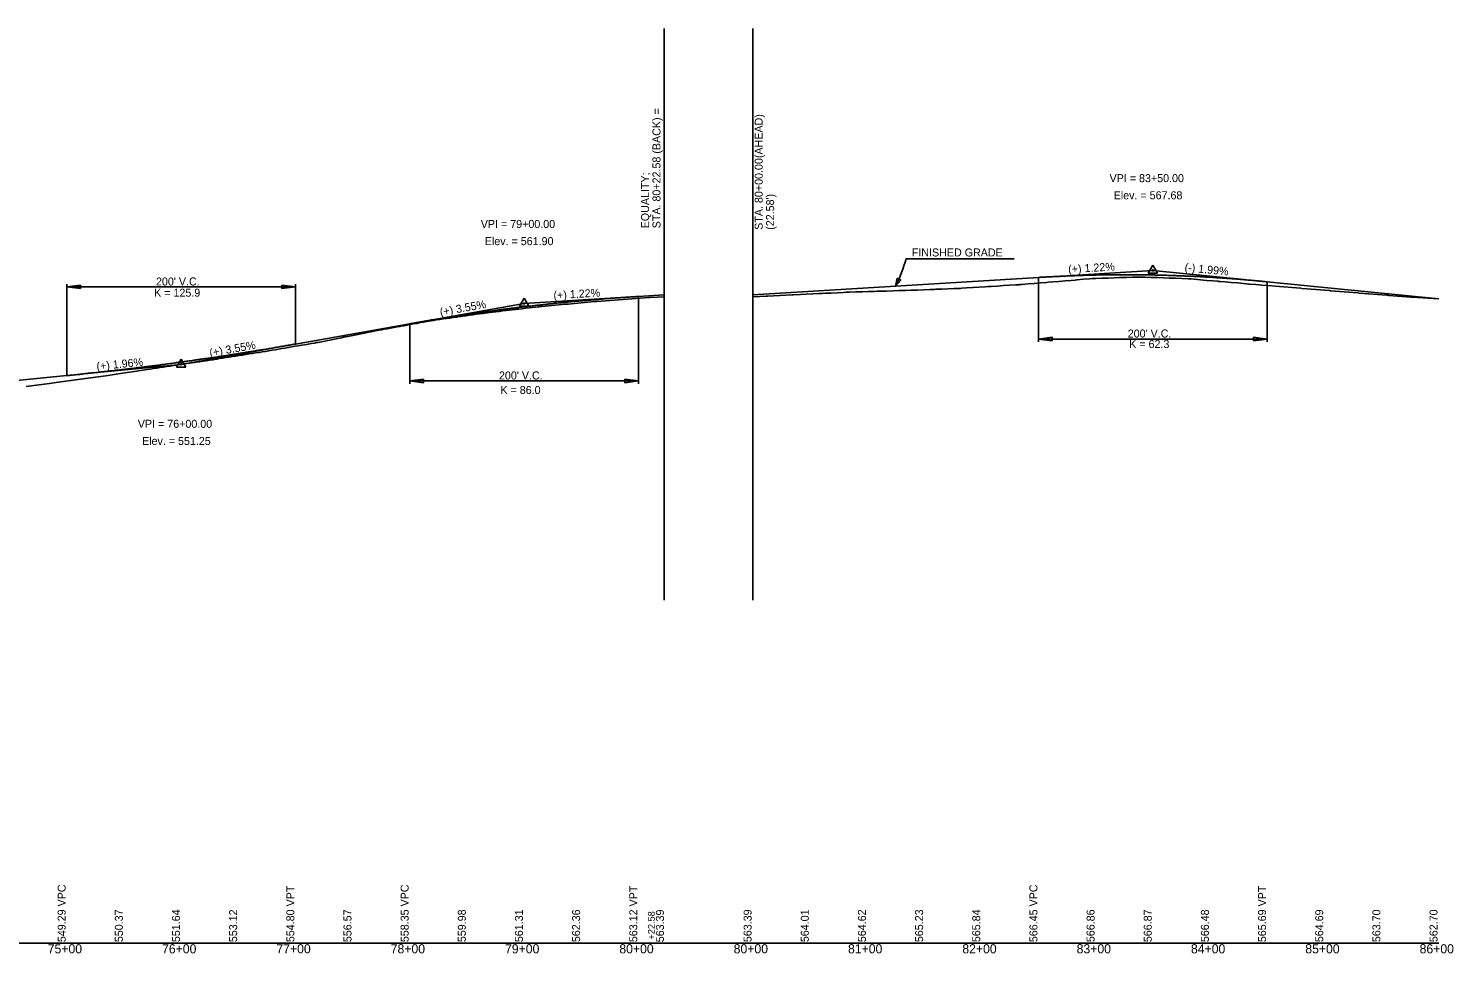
# Model space of a CAD drawing. Extents: x 49922 to 54713, y 49991 to 62800.
# Drawn here: x 53466 to 54713, y 61991 to 62800 of the extents above; entities that cross this region are included whole.
import ezdxf

# ---------------------------------------------------------------- set-up
doc = ezdxf.new("R2010")
doc.units = 0
for name, color, linetype in [('RD_DDB_GradeTX', 7, 'Continuous'), ('RD_DDB_Profile_EX', 7, 'Continuous'), ('RD_DDB_Profile_Lbl', 7, 'Continuous'), ('RD_DDB_Profile_PR', 7, 'Continuous'), ('RD_DDB_StaTX', 7, 'Continuous'), ('RD_DDB_StripGrade', 7, 'Continuous'), ('RD_DDB_VCLbl', 7, 'Continuous'), ('RD_GPK_Profile_Cell', 7, 'Continuous'), ('RD_TX_Profile', 7, 'Continuous')]:
    doc.layers.add(name, color=color, linetype=linetype)

msp = doc.modelspace()

# ---------------------------------------------------------------- linework, layer by layer
at = {"layer": 'RD_DDB_GradeTX'}
for p, q in [((54370.1, 62583.5), (54450, 62588.4)), ((54446, 62586.1), (54450, 62593)), ((54446, 62586.1), (54454, 62586.1)), ((54450, 62593), (54454, 62586.1)), ((54529.6, 62580.5), (54450, 62588.4)), ((53896, 62557.2), (53900, 62564.1)), ((53979.9, 62564.4), (53900, 62559.5)), ((53900, 62564.1), (53904, 62557.2)), ((53821.2, 62545.5), (53900, 62559.5)), ((53896, 62557.2), (53904, 62557.2)), ((53596, 62503.9), (53600, 62510.8)), ((53678.8, 62520.2), (53600, 62506.2)), ((53600, 62510.8), (53604, 62503.9)), ((53520.4, 62498.4), (53600, 62506.2)), ((53596, 62503.9), (53604, 62503.9))]:
    msp.add_line(p, q, dxfattribs=at)
for centre in [(54450, 62588.4), (53900, 62559.5), (53600, 62506.2)]:
    msp.add_circle(centre, 0.529, dxfattribs=at)
at = {"layer": 'RD_DDB_Profile_EX'}
for points in [[(54100, 62565.4), (54111.6, 62565.9), (54112.8, 62566), (54134.4, 62566.9), (54135.7, 62567), (54141.7, 62567.3), (54147.1, 62567.6), (54152.5, 62567.8), (54157.9, 62568.1), (54158.6, 62568.2), (54160.7, 62568.2), (54163.3, 62568.4), (54168.6, 62568.6), (54174, 62568.9), (54179.4, 62569.2), (54181.6, 62569.3), (54183.8, 62569.4), (54184.8, 62569.4), (54190.2, 62569.6), (54195.6, 62569.7), (54200.9, 62569.9), (54206, 62570), (54206.3, 62570), (54208.8, 62570.1), (54211.7, 62570.2), (54217.1, 62570.3), (54222.5, 62570.5), (54227.8, 62570.7), (54230.7, 62570.7), (54233.2, 62570.8), (54233.6, 62570.9), (54238.6, 62571), (54244, 62571.2), (54249.4, 62571.5), (54254.8, 62571.7), (54255.7, 62571.7), (54258.6, 62571.8), (54259.1, 62571.8), (54260.1, 62571.9), (54265.5, 62572.1), (54270.9, 62572.3), (54276.3, 62572.5), (54281, 62572.7), (54281.7, 62572.7), (54283, 62572.8), (54287.1, 62573.1), (54292.4, 62573.4), (54297.8, 62573.7), (54303.2, 62574.1), (54305.8, 62574.2), (54308, 62574.4), (54308.6, 62574.4), (54314, 62574.7), (54319.4, 62575.1), (54324.7, 62575.4), (54330.1, 62575.8), (54331.6, 62575.8), (54333, 62575.9), (54333.4, 62576), (54335.5, 62576.1), (54340.9, 62576.6), (54346.3, 62577), (54351.6, 62577.5), (54357, 62577.9), (54358.4, 62578), (54362.4, 62578.4), (54367.8, 62578.8), (54373.2, 62579.3), (54378.6, 62579.7), (54382.1, 62580), (54383.4, 62580.1), (54383.9, 62580.2), (54389.3, 62580.6), (54394.7, 62581.1), (54396.8, 62581.2), (54397.3, 62581.3), (54400.1, 62581.4), (54405.5, 62581.6), (54410.9, 62581.7), (54416.2, 62581.9), (54420.9, 62582.1), (54421.6, 62582.1), (54422.3, 62582.1), (54423.2, 62582.1), (54427, 62582.2), (54432.4, 62582.4), (54437.8, 62582.6), (54439.2, 62582.6), (54440.6, 62582.6), (54443.1, 62582.5), (54448.5, 62582.3), (54453.9, 62582.1), (54459.3, 62581.9), (54464.2, 62581.7), (54464.7, 62581.7), (54465.3, 62581.7), (54470.1, 62581.5), (54475.4, 62581.3), (54480.8, 62581.1), (54481.9, 62581), (54483.4, 62580.9)], [(54483.4, 62580.9), (54486.2, 62580.7), (54491.6, 62580.2), (54497, 62579.7), (54502.4, 62579.3), (54506.9, 62578.9), (54507.7, 62578.8), (54508.9, 62578.7), (54513.1, 62578.3), (54518.5, 62577.9), (54523.9, 62577.4), (54529.3, 62576.9), (54531.9, 62576.7), (54533.9, 62576.5), (54534.7, 62576.5), (54540, 62576), (54545.4, 62575.6), (54550.8, 62575.1), (54556.9, 62574.6), (54579.4, 62572.8), (54580.5, 62572.6), (54604.4, 62570.7), (54605.5, 62570.6), (54629.4, 62568.7), (54630.5, 62568.6), (54654.5, 62566.7), (54655.5, 62566.6), (54656.3, 62566.5), (54675.7, 62565), (54676.7, 62564.9), (54700, 62563.5)], [(53875.3, 62552.2), (53878.2, 62552.6), (53881.1, 62552.9), (53884, 62553.2), (53886.8, 62553.6), (53889.2, 62553.9), (53889.7, 62553.9), (53892.6, 62554.3), (53893.4, 62554.4), (53895.5, 62554.6), (53898.4, 62554.9), (53901.2, 62555.3), (53904.1, 62555.6), (53907, 62556), (53909.9, 62556.3), (53912.8, 62556.6), (53913.7, 62556.7), (53915.6, 62556.9), (53918.5, 62557.2), (53921.4, 62557.5), (53924.3, 62557.7), (53935.7, 62558.8), (53938.7, 62559), (53941.2, 62559.2), (53961.7, 62561.1), (53963.7, 62561.2), (53986.7, 62563), (54009.2, 62564.8), (54010.4, 62564.8), (54022.6, 62565.4)], [(53644.9, 62513), (53647.8, 62513.5), (53650.7, 62513.9), (53653.2, 62514.3), (53653.6, 62514.4), (53654.6, 62514.6), (53656.4, 62514.8), (53659.3, 62515.3), (53662.2, 62515.7), (53665.1, 62516.2), (53668, 62516.6), (53668.6, 62516.7), (53669.8, 62516.9), (53670.8, 62517.1), (53673.7, 62517.6), (53676.6, 62518.1), (53679.5, 62518.5), (53682.4, 62519), (53685.2, 62519.5), (53688.1, 62520), (53691, 62520.5), (53693.6, 62521), (53693.9, 62521), (53695, 62521.2), (53696.8, 62521.5), (53699.6, 62522), (53702.5, 62522.5), (53705.4, 62522.9), (53708.3, 62523.4), (53711.2, 62523.9), (53714, 62524.4), (53716.9, 62524.9), (53718.4, 62525.2), (53719.8, 62525.4), (53722.7, 62526), (53725.6, 62526.6), (53728.4, 62527.2), (53731.3, 62527.8), (53734.2, 62528.4), (53737.1, 62528.9), (53740, 62529.5), (53743.1, 62530.2), (53743.5, 62530.2), (53745.7, 62530.7), (53748.6, 62531.3), (53751.5, 62531.8), (53754.5, 62532.4), (53757.2, 62533), (53760.1, 62533.5), (53763, 62534.1), (53765.6, 62534.6), (53765.9, 62534.6), (53766.3, 62534.7), (53768.8, 62535.2), (53771.6, 62535.8), (53774.5, 62536.3), (53775.4, 62536.5), (53777.4, 62536.9), (53780.3, 62537.4), (53783.2, 62537.9), (53786, 62538.4), (53788.9, 62539), (53791.2, 62539.4), (53791.8, 62539.5), (53792.1, 62539.6), (53794.7, 62540), (53797.6, 62540.6), (53800.4, 62541.1), (53803.3, 62541.6), (53806.2, 62542.1), (53809.1, 62542.7), (53812, 62543.2), (53814.8, 62543.7), (53816.3, 62544), (53817.9, 62544.3), (53818.6, 62544.4), (53820.6, 62544.7), (53823.5, 62545.1), (53826.4, 62545.5), (53829.2, 62545.9), (53832.1, 62546.3), (53835, 62546.7), (53837.9, 62547.2), (53840.8, 62547.6), (53841.8, 62547.7), (53843.6, 62548), (53844.9, 62548.1), (53846.5, 62548.3), (53849.4, 62548.7), (53852.3, 62549.2), (53855.2, 62549.6), (53858, 62550), (53860.9, 62550.4), (53863.8, 62550.8), (53864.6, 62550.9), (53865.7, 62551), (53866.7, 62551.2), (53867.9, 62551.3), (53869.6, 62551.5), (53872.4, 62551.9), (53875.3, 62552.2)], [(53464.5, 62486.9), (53484.9, 62489.6), (53492.7, 62490.7), (53509.8, 62493), (53520.8, 62494.4), (53534.1, 62496.2), (53548.8, 62498.5), (53559.1, 62499.9), (53570, 62501.6), (53572.9, 62502.1), (53575.8, 62502.5), (53577.7, 62502.8), (53578.7, 62503), (53581.6, 62503.4), (53584, 62503.7), (53584.4, 62503.8), (53587.3, 62504.2), (53590.2, 62504.7), (53593.1, 62505.1), (53596, 62505.6), (53598.8, 62506), (53601.7, 62506.4), (53604.6, 62506.9), (53605.1, 62506.9), (53607.5, 62507.3), (53609, 62507.5), (53610.4, 62507.7), (53611.5, 62507.8), (53613.2, 62508.1), (53616.1, 62508.5), (53619, 62508.9), (53621.9, 62509.4), (53624.8, 62509.8), (53627.6, 62510.2), (53628, 62510.3), (53630.5, 62510.7), (53631.1, 62510.8), (53633.4, 62511.2), (53636.3, 62511.6), (53639.2, 62512.1), (53642, 62512.6), (53644.9, 62513)]]:
    msp.add_lwpolyline(points, dxfattribs=at)
at = {"layer": 'RD_DDB_Profile_PR'}
for p, q in [((54100, 62567), (54350, 62582.3)), ((54550, 62578.4), (54700, 62563.5)), ((54000, 62565.6), (54022.6, 62567)), ((53700, 62524), (53800, 62541.7)), ((53300, 62476.8), (53500, 62496.4))]:
    msp.add_line(p, q, dxfattribs=at)
for points in [[(54350, 62582.3), (54354, 62582.5), (54358, 62582.7), (54362, 62582.9), (54366, 62583.1), (54370, 62583.3), (54374, 62583.5), (54378, 62583.7), (54382, 62583.8), (54386, 62583.9), (54390, 62584.1), (54394, 62584.2), (54398, 62584.3), (54402, 62584.4), (54406, 62584.4), (54410, 62584.5), (54414, 62584.5), (54418, 62584.6), (54422, 62584.6), (54426, 62584.6), (54430, 62584.6), (54434, 62584.6), (54438, 62584.5), (54442, 62584.5), (54446, 62584.4), (54450, 62584.4), (54454, 62584.3), (54458, 62584.2), (54462, 62584.1), (54466, 62584), (54470, 62583.8), (54474, 62583.7), (54478, 62583.5), (54482, 62583.3), (54486, 62583.2), (54490, 62583), (54494, 62582.7), (54498, 62582.5), (54502, 62582.3), (54506, 62582), (54510, 62581.8), (54514, 62581.5), (54518, 62581.2), (54522, 62580.9), (54526, 62580.6), (54530, 62580.3), (54534, 62579.9), (54538, 62579.6), (54542, 62579.2), (54546, 62578.8), (54550, 62578.4)], [(53800, 62541.7), (53804, 62542.4), (53808, 62543.1), (53812, 62543.8), (53816, 62544.5), (53820, 62545.2), (53824, 62545.8), (53828, 62546.5), (53832, 62547.1), (53836, 62547.7), (53840, 62548.4), (53844, 62549), (53848, 62549.6), (53852, 62550.2), (53856, 62550.8), (53860, 62551.3), (53864, 62551.9), (53868, 62552.5), (53872, 62553), (53876, 62553.5), (53880, 62554.1), (53884, 62554.6), (53888, 62555.1), (53892, 62555.6), (53896, 62556.1), (53900, 62556.6), (53904, 62557), (53908, 62557.5), (53912, 62558), (53916, 62558.4), (53920, 62558.8), (53924, 62559.3), (53928, 62559.7), (53932, 62560.1), (53936, 62560.5), (53940, 62560.9), (53944, 62561.3), (53948, 62561.6), (53952, 62562), (53956, 62562.3), (53960, 62562.7), (53964, 62563), (53968, 62563.3), (53972, 62563.7), (53976, 62564), (53980, 62564.3), (53984, 62564.5), (53988, 62564.8), (53992, 62565.1), (53996, 62565.3), (54000, 62565.6)], [(53500, 62496.4), (53504, 62496.8), (53508, 62497.2), (53512, 62497.6), (53516, 62498.1), (53520, 62498.5), (53524, 62498.9), (53528, 62499.3), (53532, 62499.8), (53536, 62500.2), (53540, 62500.7), (53544, 62501.1), (53548, 62501.6), (53552, 62502.1), (53556, 62502.5), (53560, 62503), (53564, 62503.5), (53568, 62504), (53572, 62504.5), (53576, 62505), (53580, 62505.5), (53584, 62506.1), (53588, 62506.6), (53592, 62507.1), (53596, 62507.7), (53600, 62508.2), (53604, 62508.8), (53608, 62509.3), (53612, 62509.9), (53616, 62510.5), (53620, 62511.1), (53624, 62511.6), (53628, 62512.2), (53632, 62512.8), (53636, 62513.4), (53640, 62514), (53644, 62514.7), (53648, 62515.3), (53652, 62515.9), (53656, 62516.6), (53660, 62517.2), (53664, 62517.9), (53668, 62518.5), (53672, 62519.2), (53676, 62519.8), (53680, 62520.5), (53684, 62521.2), (53688, 62521.9), (53692, 62522.6), (53696, 62523.3), (53700, 62524)]]:
    msp.add_spline(points, degree=3, dxfattribs=at)
at = {"layer": 'RD_DDB_VCLbl'}
for p, q in [((54022.6, 62300), (54022.6, 62800)), ((54022.6, 62300), (54022.6, 62800)), ((54100, 62300), (54100, 62800)), ((53500, 62576.5), (53500, 62496.4)), ((53512, 62575.5), (53500, 62574)), ((53500, 62574), (53700, 62574)), ((53500, 62574), (53512, 62572.5)), ((53512, 62572.5), (53512, 62575.5)), ((53700, 62574), (53688, 62575.5)), ((53688, 62575.5), (53688, 62572.5)), ((53688, 62572.5), (53700, 62574)), ((53700, 62576.5), (53700, 62524)), ((54350, 62525.9), (54350, 62582.3)), ((54550, 62525.9), (54550, 62578.4)), ((54000, 62489.2), (54000, 62565.6)), ((54022.6, 62565.4), (54022.6, 62565.4)), ((54022.6, 62565.4), (54022.6, 62565.4)), ((53800, 62489.2), (53800, 62541.7)), ((54362, 62529.9), (54350, 62528.4)), ((54350, 62528.4), (54550, 62528.4)), ((54350, 62528.4), (54362, 62526.9)), ((54362, 62526.9), (54362, 62529.9)), ((54550, 62528.4), (54538, 62529.9)), ((54538, 62529.9), (54538, 62526.9)), ((54538, 62526.9), (54550, 62528.4)), ((53812, 62493.2), (53800, 62491.7)), ((53800, 62491.7), (54000, 62491.7)), ((53800, 62491.7), (53812, 62490.2)), ((53812, 62490.2), (53812, 62493.2)), ((54000, 62491.7), (53988, 62493.2)), ((53988, 62493.2), (53988, 62490.2)), ((53988, 62490.2), (54000, 62491.7))]:
    msp.add_line(p, q, dxfattribs=at)
at = {"layer": 'RD_GPK_Profile_Cell'}
msp.add_line((50000, 62000), (54700, 62000), dxfattribs=at)
at = {"layer": 'RD_TX_Profile'}
msp.add_line((54328.7, 62598.6), (54234.1, 62598.6), dxfattribs=at)
msp.add_lwpolyline([(54226.3, 62581.5), (54225, 62574.6), (54229.5, 62579.9)], close=True, dxfattribs=at)
msp.add_arc((54084.2, 62641.8), 156, 334.5045, 343.945, dxfattribs=at)

# ---------------------------------------------------------------- texts
at = {"layer": 'RD_DDB_GradeTX'}
for s, rotation, p in [('(+) 1.22%', 3.4998, (54376.1, 62585.9)), ('(-) 1.99%', 354.3227, (54477.5, 62587.7)), ('(+) 3.55%', 10.0633, (53826.9, 62548.5)), ('(+) 1.22%', 3.4998, (53925.9, 62563.1)), ('(+) 3.55%', 10.0633, (53625.4, 62512.8)), ('(+) 1.96%', 5.5985, (53526.3, 62501))]:
    msp.add_text(s, height=7, rotation=rotation, dxfattribs=at).set_placement(p)
at = {"layer": 'RD_DDB_Profile_Lbl'}
for s, p in [('VPI = 83+50.00', (54412.1, 62665.6)), ('Elev. = 567.68', (54415.7, 62650.6)), ('VPI = 79+00.00', (53862.1, 62625.5)), ('Elev. = 561.90', (53865.6, 62610.5)), ('VPI = 76+00.00', (53562.1, 62450.7)), ('Elev. = 551.25', (53565.8, 62435.7))]:
    msp.add_text(s, height=7, dxfattribs=at).set_placement(p)
at = {"layer": 'RD_DDB_StaTX'}
for s, p in [('75+00', (53483.3, 61991)), ('76+00', (53583.3, 61991)), ('77+00', (53683.3, 61991)), ('78+00', (53783.3, 61991)), ('79+00', (53883.3, 61991)), ('80+00', (53983.3, 61991)), ('80+00', (54083.3, 61991)), ('81+00', (54183.3, 61991)), ('82+00', (54283.3, 61991)), ('83+00', (54383.3, 61991)), ('84+00', (54483.3, 61991)), ('85+00', (54583.3, 61991)), ('86+00', (54683.3, 61991))]:
    msp.add_text(s, height=8, dxfattribs=at).set_placement(p)
at = {"layer": 'RD_DDB_StripGrade'}
for s, p in [('549.29 VPC', (53499, 62000.8)), ('554.80 VPT', (53699, 62000.8)), ('558.35 VPC', (53799, 62000.8)), ('563.12 VPT', (53999, 62000.8)), ('566.45 VPC', (54349, 62000.8)), ('565.69 VPT', (54549, 62000.8)), ('549.29', (53499, 62000.8)), ('550.37', (53549, 62000.8)), ('551.64', (53599, 62000.8)), ('553.12', (53649, 62000.8)), ('554.80', (53699, 62000.8)), ('556.57', (53749, 62000.8)), ('558.35', (53799, 62000.8)), ('559.98', (53849, 62000.8)), ('561.31', (53899, 62000.8)), ('562.36', (53949, 62000.8)), ('563.12', (53999, 62000.8)), ('563.39', (54022.3, 62000.7)), ('563.39', (54099, 62000.8)), ('563.39', (54099, 62000.8)), ('564.01', (54149, 62000.8)), ('564.62', (54199, 62000.8)), ('565.23', (54249, 62000.8)), ('565.84', (54299, 62000.8)), ('566.45', (54349, 62000.8)), ('566.86', (54399, 62000.8)), ('566.87', (54449, 62000.8)), ('566.48', (54499, 62000.8)), ('565.69', (54549, 62000.8)), ('564.69', (54599, 62000.8)), ('563.70', (54649, 62000.8)), ('562.70', (54699, 62000.8))]:
    msp.add_text(s, height=7, rotation=90, dxfattribs=at).set_placement(p)
at = {"layer": 'RD_DDB_VCLbl'}
for s, p in [("200' V.C.", (53578, 62575.2)), ('K = 125.9', (53576.4, 62565.4)), ("200' V.C.", (54428, 62529.7)), ('K = 62.3', (54429.3, 62520.5)), ("200' V.C.", (53878, 62493)), ('K = 86.0', (53879.3, 62480.3))]:
    msp.add_text(s, height=7, dxfattribs=at).set_placement(p)
at = {"layer": 'RD_TX_Profile'}
for s, height, p in [('STA. 80+22.58 (BACK) =', 7, (54019.3, 62625.2)), ('STA. 80+00.00(AHEAD)', 7, (54108.7, 62623.9)), ('EQUALITY;', 7, (54009.3, 62625.2)), ("(22.58')", 7, (54118.7, 62623.9)), ('+22.58', 6, (54014.3, 62003.1))]:
    msp.add_text(s, height=height, rotation=90, dxfattribs=at).set_placement(p)
msp.add_text('FINISHED GRADE', height=7, dxfattribs=at).set_placement((54239.1, 62600.6))

doc.saveas('drawing.dxf')
